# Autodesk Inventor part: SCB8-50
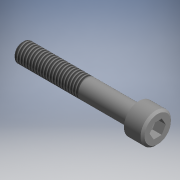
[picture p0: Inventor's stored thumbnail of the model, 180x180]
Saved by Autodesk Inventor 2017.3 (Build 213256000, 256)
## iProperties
Part Number: SCB8-50
Material: Generic
Catalog Web Link: www.cadenas.de
Description: SCB-Hexagon Socket Head Cap Screws - Stainless Steel
Vendor: MISUMI
Document SubType Name: Modeling
Designer: partserver
Manufacturer: MISUMI
Mass: 3.42127 g
Surface Area: 18.9919 cm^2
Volume: 3.42127 cm^3
Density: 1 g/cm^3
Appearance: PSOLRGB-175-175-175
Category: PARTsolutions
Company: MISUMI
Title: SCB8-50
Author: Cadenas PARTsolutions
Comments: Hexagon Socket Head Cap Screws - Stainless Steel
PSOL_IDENT_0: {$CADENAS_DATA\23d-libs\misumi\metric\27_screws_nuts\scb_fa.prj},154 {VTYP=3D},{NB=SCB8-50},{LINA=SC
PSOL_IDENT_1: B8-50},{NN=SCB},{DATE=03.06.2021 03:35:43},{GEOMDATE=23.02.2012 00:00:00},{VERSION=},{LINEID=110},{W
PSOL_IDENT_2: BVAR=L},{WBNUMERIC=L}  {NB=SCB8-50},{LINA=SCB8-50},{KT=DUMMY},{PN=SCB8-50},{MAT=SUSXM7(30430 Stainle
PSOL_IDENT_3: ss Steel)},{SC=A2-70},{M=8},{L=50},{LL=28},{L1=28},{TYPE=SCB},{M1=8.0},{L0=10,12,14,15,16,18,20,22,2
PSOL_IDENT_4: 5,30,35,40,45,50,55,60,65,70,75,80},{MP=8x1.25},{P=1.25},{A=13.0},{E=8.0},{B=6.0},{V=0.80}
NB: SCB8-50
NN: SCB
NT: Hexagon Socket Head Cap Screws - Stainless Steel
NBSYN: $PN.
LINA: SCB8-50
CATALOG: Misumi
PN: SCB8-50
MAT: 302HQ Stainless Steel
SC: A2-70
M: 8
L: 50
LL: 28
MP: 8x1.25
A: 13
E: 8
B: 6
SUPPLIER: MISUMI
ARTICLENO: SCB8-50
BOMINFO: SCB8-50
CREATOR: CADENAS GmbH
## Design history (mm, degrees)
sketch "Sketch_2"
  geometry: L1 (50, 0)-(-8, 0); L2 (-8, 0)-(-8, 5.633); L3 (-8, 5.633)-(-7.133, 6.5); L4 (-7.133, 6.5)-(0, 6.5); L5 (0, 6.5)-(0, 4); L6 (0, 4)-(49.233, 4); L7 (49.233, 4)-(50, 3.233); L8 (50, 3.233)-(50, 0); L9 (50, 0)-(-8, 0)
  constraints: 18 end point
revolve "Revolution1" sketch "Sketch_2" stored, may be unused: angle "d0" = 360 deg
thread "Thread1" dims "d1" = 27.233, "d2" = 0
sketch "Sketch2"
  geometry: 1 further point
hole "Hole1" sketch "Sketch2" at (0, 0) diameter "d3" = 6; stored, may be unused: countersink angle "d7" = 90 deg, drill point angle "d9" = 150 deg; dims "d4" = 6, "d5" = 4, "d6" = 2, "d8" = 4
sketch "Sketch_3"
  geometry: L1 (-3, -1.732)-(0, -3.464); L2 (0, -3.464)-(3, -1.732); L3 (3, -1.732)-(3, 1.732); L4 (3, 1.732)-(0, 3.464); L5 (0, 3.464)-(-3, 1.732); L6 (-3, 1.732)-(-3, -1.732)
  constraints: 12 end point
extrude "Extrusion1" cut sketch "Sketch_3" distance "d10" = 4; taper "d11" = 0 deg
node "bolt_XY"
node "bolt_YZ"
node "bolt_ZX"
node "bolt_X"
node "bolt_Y"
node "bolt_Z"
node "bolt_Center"
node "nut_XY"
node "nut_YZ"
node "nut_ZX"
node "nut_X"
node "nut_Y"
node "nut_Z"
node "nut_Center"
body "Solid1"
other parameters: "d12" = 0, "d13" = 0
